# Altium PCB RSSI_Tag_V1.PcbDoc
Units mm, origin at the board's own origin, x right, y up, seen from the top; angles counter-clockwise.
Board outline 76.2 x 83.52 mm, 2 copper layers (Top Layer, Bottom Layer); 76 components, 47 nets, 358 pads, 24 vias.
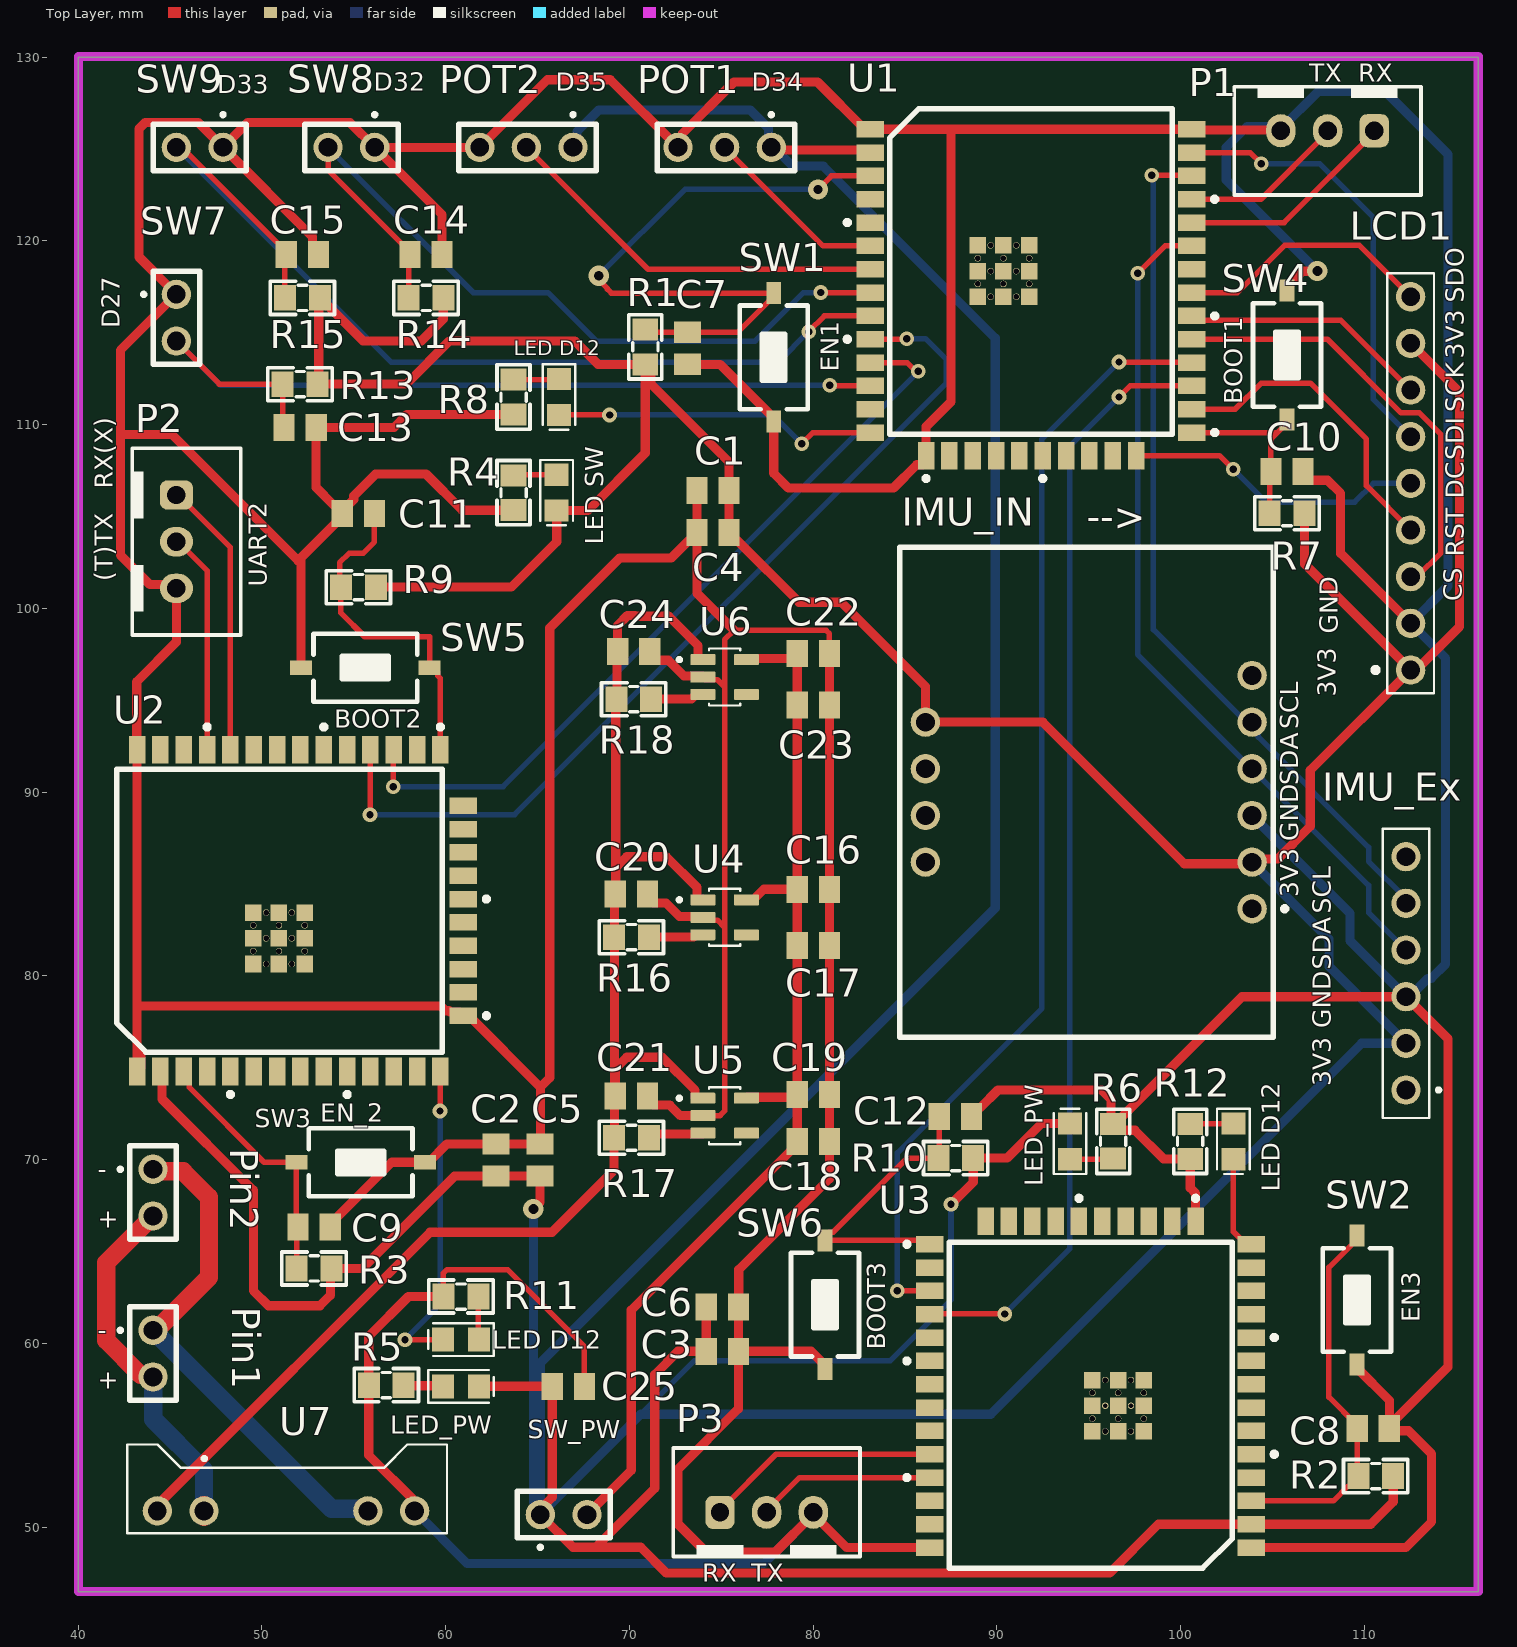
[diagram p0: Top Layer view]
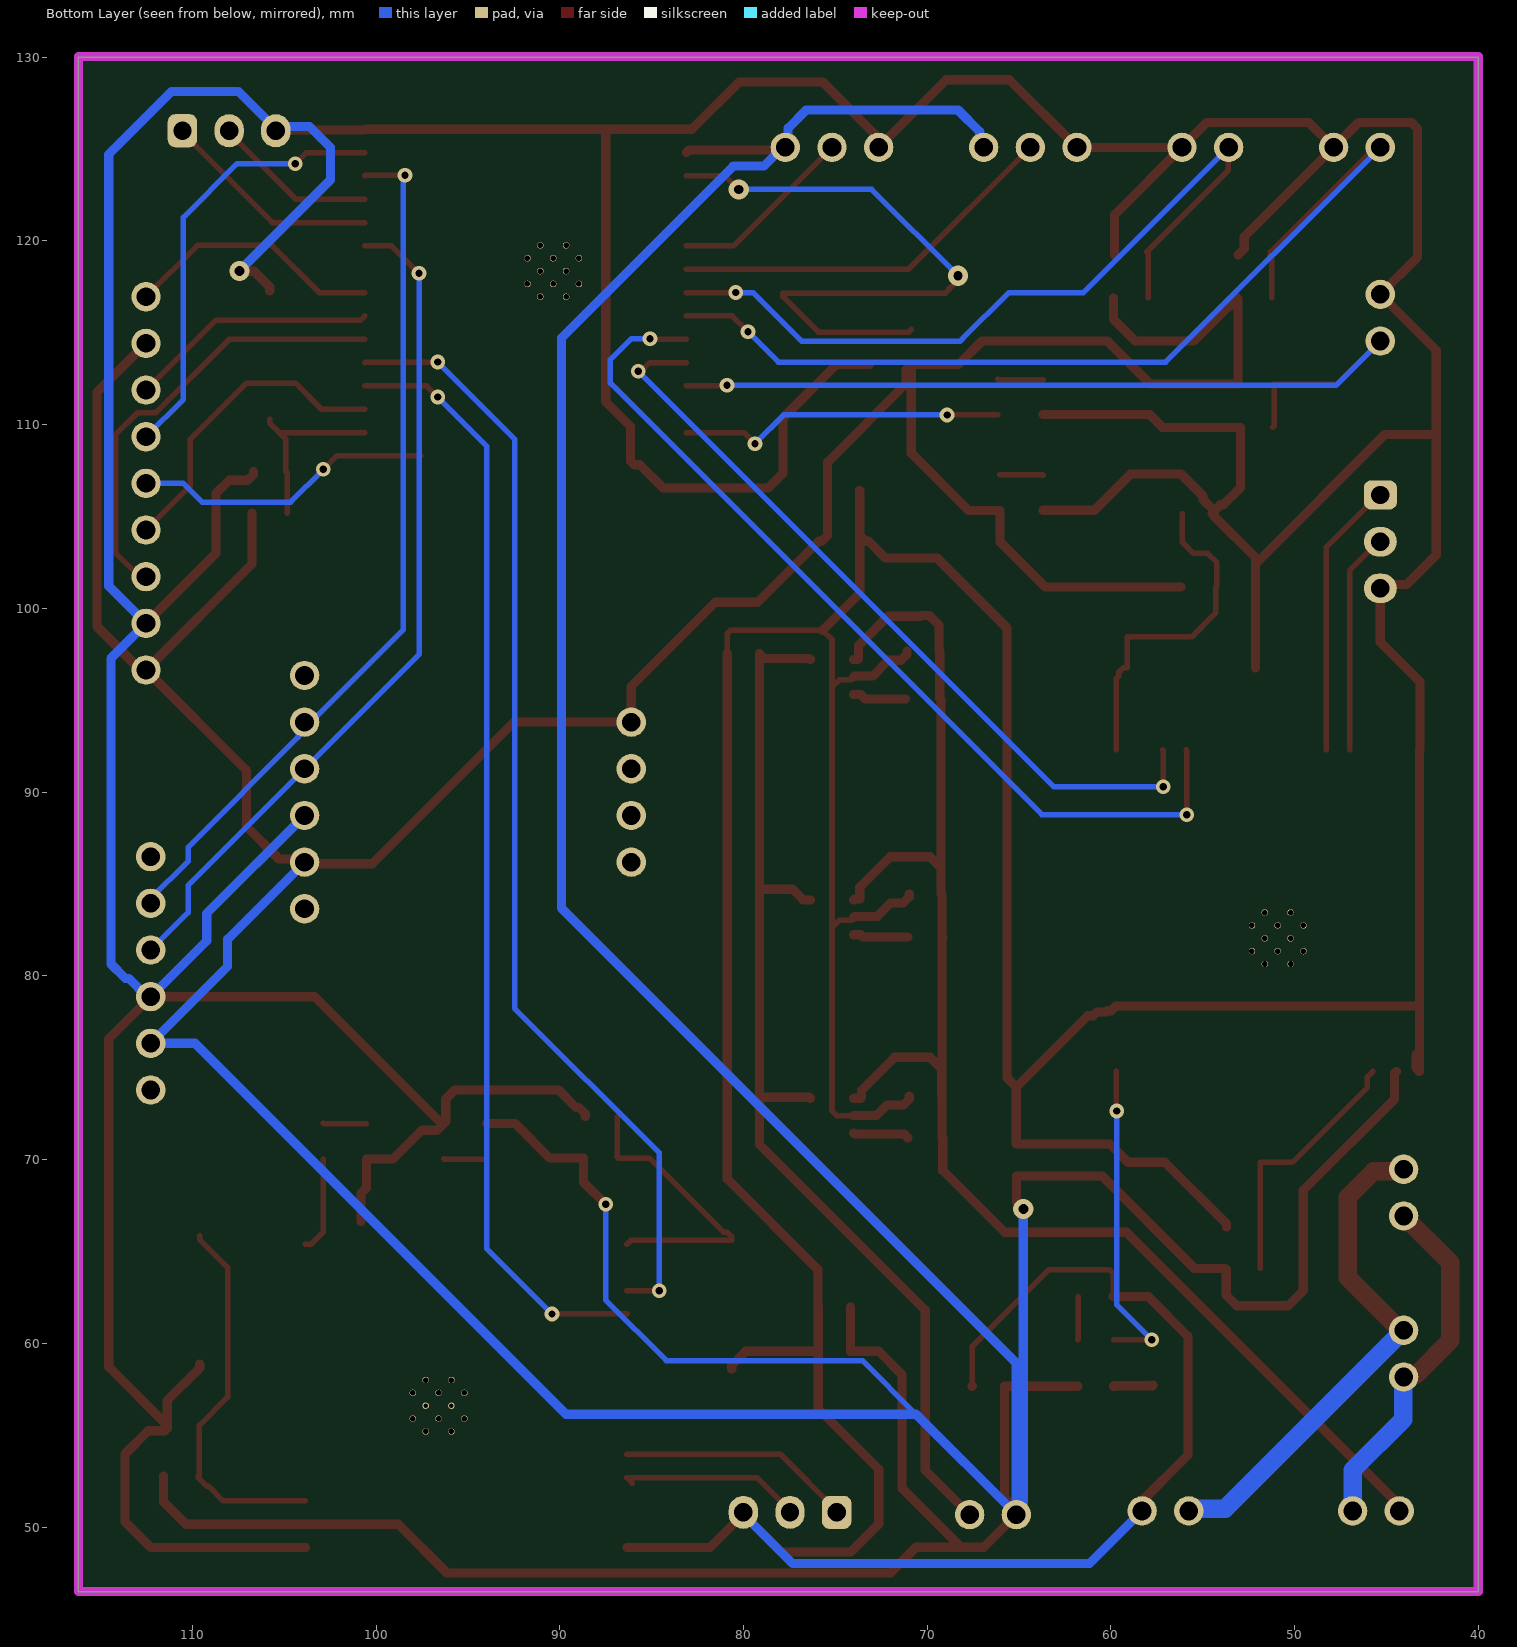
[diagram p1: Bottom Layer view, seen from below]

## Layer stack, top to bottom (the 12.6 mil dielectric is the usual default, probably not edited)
Top Solder: solder mask 0.0102, Solder Resist, Dk 3.5
Top Layer: signal copper 0.0356
Dielectric 1: dielectric 0.32, FR-4, Dk 4.8
Bottom Layer: signal copper 0.0356
Bottom Solder: solder mask 0.0102, Solder Resist, Dk 3.5

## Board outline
40.005,46.482 40.005,130 116.205,130 116.205,46.482

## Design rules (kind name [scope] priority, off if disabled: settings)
Clearance [All] p1: gap=0.3 ignorepadtopadclearanceinfootprint=FALSE
PolygonConnect [All] p1: connectstyle=Relief reliefconductorwidth=0.254 reliefentries=4 polygonreliefangle="90 Angle" airgapwidth=0.254
RoutingVias [All] p1: holewidth=0.711 width=1.27 viastyle="Through Hole" minholewidth=0.711 minwidth=1.27 maxholewidth=0.711 maxwidth=1.27
SolderMaskExpansion [All] p1: expansion=0.102 istentingtop=FALSE
Width POW [InNetClass('POW')] p1: maxlimit=1 minlimit=0.3 preferedwidth=0.5
Width RON [InNetClass('RON')] p2: maxlimit=0.5 minlimit=0.3 preferedwidth=0.3
30 further rules are at their usual default settings.

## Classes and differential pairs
net class RON: BOOT BOOT_2 BOOT_3 D2/SPI_DC D4/SPI_RST D5/SPI_CS D12/LED1 D12/LED1_2 D12/LED1_3 D18/SPI_SCK D19/SPI_SDO D23/SPI_SDI D27 D32 D33 D34_Pot1 D35_Pot2 EN EN_2 EN_3 NetLED1_2 NetLED2_2 NetLED3_2 NetLED4_2 NetLED5_2 NetLED6_2 NetR16_2 NetR17_2 NetR18_2 RX0 RX0_2 RX0_3 RX1/TX2_2 RX2/TX2_3 SCL SDA TX0 TX0_2 TX0_3 TX1/RX2_2 TX2_RX2_3
net class POW: 3V3 GND O_3V3 VBAT+ VBAT- VOUT

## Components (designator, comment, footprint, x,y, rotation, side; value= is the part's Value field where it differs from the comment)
C1 "10uF" Capacitor_0805 74.549,106.426 r180 top
C2 "10uF" Capacitor_0805 62.738,69.977 r90 top
C3 "10uF" Capacitor_0805 75.057,59.563 r0 top
C4 "0.1uF" Capacitor_0805 74.549,104.14 r180 top
C5 "0.1uF" Capacitor_0805 65.138,69.977 r90 top
C6 "0.1uF" Capacitor_0805 75.057,61.976 r0 top
C7 "10uF" Capacitor_0805 73.152,114.159 r270 top
C8 "10uF" Capacitor_0805 110.49,55.372 r0 top
C9 "10uF" Capacitor_0805 52.832,66.335 r0 top
C10 "10uF" Capacitor_0805 105.791,107.442 r0 top
C11 "10uF" Capacitor_0805 55.245,105.156 r180 top
C12 "10uF" Capacitor_0805 87.743,72.341 r0 top
C13 "10uF" Capacitor_0805 52.07,109.855 r0 top
C14 "10uF" Capacitor_0805 58.928,119.253 r0 top
C15 "10uF" Capacitor_0805 52.197,119.253 r0 top
C16 "47uF" Capacitor_0805 80.01,84.709 r0 top
C17 "0.1uF" Capacitor_0805 80.01,81.661 r0 top
C18 "47uF" Capacitor_0805 80.01,70.993 r0 top
C19 "0.1uF" Capacitor_0805 80.01,73.533 r0 top
C20 "0.1uF" Capacitor_0805 70.104,84.455 r0 top
C21 "0.1uF" Capacitor_0805 70.104,73.447 r0 top
C22 "47uF" Capacitor_0805 80.01,97.536 r0 top
C23 "0.1uF" Capacitor_0805 80.01,94.742 r0 top
C24 "0.1uF" Capacitor_0805 70.231,97.663 r0 top
C25 "0.1uF" Capacitor_0805 66.675,57.658 r0 top
IMU_Ex "BNO055" BNO055_External 112.268,80.137 r90 top (schematic designator IMU_Ex1)
IMU_IN "BNO055" BNO055_Internal 95,90 r90 top
LCD1 "ILI9341" ILI9341_LCD3.5 112.522,106.807 r0 top
"LED D12" "Led" "Led 0805 Blue" 102.87,70.993 r90 top (schematic designator LED6)
"LED D12" "Led" "Led 0805 Blue" 60.833,60.198 r0 top (schematic designator LED5)
"LED D12" "Led" "Led 0805 Blue" 66.167,111.506 r90 top (schematic designator LED4)
"LED SW" "Led" "Led 0805 Blue" 66.04,106.299 r90 top (schematic designator LED1)
LED_PW "Led" "Led 0805 Blue" 93.98,70.993 r270 top (schematic designator LED3)
LED_PW "Led" "Led 0805 Blue" 60.833,57.658 r180 top (schematic designator LED2)
P1 "UART" HDR/Header/3/BOX 108,126 r270 top
P2 "UART" HDR/Header/3/BOX 45.339,103.632 r0 top
P3 "UART" HDR/Header/3/BOX 77.47,50.8 r90 top
Pin1 "JP_1x2" JP_1x2 44.069,59.436 r270 top (schematic designator Battery1)
Pin2 "JP_1x2" JP_1x2 44.069,68.199 r270 top (schematic designator Battery2)
POT1 "JP_1x3" JP_1x3 79.121,119.634 r180 top
POT2 "JP_1x3" JP_1x3 68.326,119.634 r180 top
R1 "10k" "tro smd 0805" 70.927,114.238 r270 top
R2 "10k" "tro smd 0805" 110.617,52.832 r0 top
R3 "10k" "tro smd 0805" 52.832,64.135 r0 top
R4 "1k" "tro smd 0805" 63.754,106.299 r270 top
R5 "1k" "tro smd 0805" 56.769,57.658 r180 top
R6 "1k" "tro smd 0805" 96.266,70.993 r90 top
R7 "10k" "tro smd 0805" 105.791,105.242 r0 top
R8 "1k" "tro smd 0805" 63.754,111.506 r270 top
R9 "10k" "tro smd 0805" 55.245,101.219 r0 top
R10 "10k" "tro smd 0805" 87.757,70.14 r0 top
R11 "1k" "tro smd 0805" 60.833,62.484 r180 top
R12 "1k" "tro smd 0805" 100.584,70.993 r270 top
R13 "10k" "tro smd 0805" 52.07,112.268 r0 top
R14 "10k" "tro smd 0805" 58.928,116.967 r0 top
R15 "10k" "tro smd 0805" 52.197,116.967 r0 top
R16 "1k" "tro smd 0805" 70.104,82.169 r0 top
R17 "1k" "tro smd 0805" 70.104,71.247 r0 top
R18 "1k" "tro smd 0805" 70.231,95.123 r0 top
SW1 "SW" SW1-SMD 77.851,113.665 r90 top value="SW chip 2 pin"
SW2 "SW" SW1-SMD 109.601,62.357 r90 top value="SW chip 2 pin"
SW3 "SW" SW1-SMD 55.372,69.85 r180 top value="SW chip 2 pin"
SW4 "SW" SW1-SMD 105.791,113.792 r270 top value="SW chip 2 pin"
SW5 "SW" SW1-SMD 55.626,96.774 r0 top value="SW chip 2 pin"
SW6 "SW" SW1-SMD 80.645,62.103 r90 top value="SW chip 2 pin"
SW7 "JP_1x2" JP_1x2 45.339,115.824 r270 top
SW8 "JP_1x2" JP_1x2 54.864,125.095 r180 top
SW9 "JP_1x2" JP_1x2 46.609,125.095 r180 top
SW_PW "SW_POWER" JP_1x2 66.421,50.673 r0 top (schematic designator jp_1)
U1 "ESP32_WROOM_32U" ESP32_WROOM_32U#1 91.859,117.201 r0 top
U2 "ESP32_WROOM_32U" ESP32_WROOM_32U#1 52.084,83.545 r90 top
U3 "ESP32_WROOM_32U" ESP32_WROOM_32U#2 95.1,57.76 r180 top
U4 "AP2112K-3.3TRG1" SOT95P285X140-5N 75.184,83.185 r0 top
U5 "AP2112K-3.3TRG1" SOT95P285X140-5N 75.184,72.39 r0 top
U6 "AP2112K-3.3TRG1" SOT95P285X140-5N 75.184,96.266 r0 top
U7 "TP4056_charger" TP4056_charger 51.305,39.376 r90 top

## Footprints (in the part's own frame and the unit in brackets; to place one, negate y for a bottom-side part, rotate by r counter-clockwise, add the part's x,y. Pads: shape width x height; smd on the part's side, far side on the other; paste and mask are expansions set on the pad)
BNO055_External [mm]
  round 1.6 hole 1.02 mask+0.1: 1(-6.35,0) 2(-3.81,0) 3(-1.27,0) 4(1.27,0) 5(3.81,0) 6(6.35,0)
  silkscreen extent -7.87,-1.88 7.87,1.27, body extent -8.75,-2.16 8.75,3.59, height 7.1
BNO055_Internal [mm]
  round 1.6 hole 1.02 mask+0.1: 1(-6.35,-8.89) 2(-3.81,-8.89) 3(-1.27,-8.89) 4(1.27,-8.89) 5(3.81,-8.89) 6(6.35,-8.89) 7(3.81,8.89) 8(1.27,8.89) 9(-1.27,8.89) 10(-3.81,8.89)
  silkscreen extent -13.33,-10.77 13.33,10.29, body extent -13.33,-10.12 13.33,10.29, height 9.15
Capacitor_0805 [mm]
  rect 1.16x1.47 smd: 1(-0.875,0) 2(0.875,0)
  body extent -1,-0.6 1,0.6, height 1.2
ESP32_WROOM_32U#1 [mm]
  rect 1.5x0.9 smd: 1(-8.75,8.88) 2(-8.75,7.61) 3(-8.75,6.34) 4(-8.75,5.07) 5(-8.75,3.8) 6(-8.75,2.53) 7(-8.75,1.26) 8(-8.75,-0.01) 9(-8.75,-1.28) 10(-8.75,-2.55) 11(-8.75,-3.82) 12(-8.75,-5.09) 13(-8.75,-6.36) 14(-8.75,-7.63) 25(8.75,-7.63) 26(8.75,-6.36) 27(8.75,-5.09) 28(8.75,-3.82) 29(8.75,-2.55) 30(8.75,-1.28) 31(8.75,-0.01) 32(8.75,1.26) 33(8.75,2.53) 34(8.75,3.8) 35(8.75,5.07) 36(8.75,6.34) 37(8.75,7.61) 38(8.75,8.88)
  rect 0.9x1.5 smd: 15(-5.715,-8.88) 16(-4.445,-8.88) 17(-3.175,-8.88) 18(-1.905,-8.88) 19(-0.635,-8.88) 20(0.635,-8.88) 21(1.905,-8.88) 22(3.175,-8.88) 23(4.445,-8.88) 24(5.715,-8.88)
  rect 0.9x0.9 smd: 39_1(-2.9,2.56) 39_2(-1.5,2.56) 39_3(-0.1,2.56) 39_4(-2.9,1.16) 39_5(-1.5,1.16) 39_6(-0.1,1.16) 39_7(-2.9,-0.24) 39_8(-1.5,-0.24) 39_9(-0.1,-0.24)
  round 0.35 hole 0.3 mask+0: 40_1(-2.2,2.56) 40_2(-0.8,2.56) 40_3(-2.9,1.86) 40_4(-1.5,1.86) 40_5(-0.1,1.86) 40_6(-2.2,1.16) 40_7(-0.8,1.16) 40_8(-2.9,0.46) 40_9(-1.5,0.46) 40_10(-0.1,0.46) 40_11(-2.2,-0.24) 40_12(-0.8,-0.24)
  silkscreen extent -10.1,-10.23 10.1,10, body extent -9,-9.13 9,10.07, height 3.35
ESP32_WROOM_32U#2 [mm]
  rect 1.5x0.9 smd: 1(-8.75,8.88) 2(-8.75,7.61) 3(-8.75,6.34) 4(-8.75,5.07) 5(-8.75,3.8) 6(-8.75,2.53) 7(-8.75,1.26) 8(-8.75,-0.01) 9(-8.75,-1.28) 10(-8.75,-2.55) 11(-8.75,-3.82) 12(-8.75,-5.09) 13(-8.75,-6.36) 14(-8.75,-7.63) 25(8.75,-7.63) 26(8.75,-6.36) 27(8.75,-5.09) 28(8.75,-3.82) 29(8.75,-2.55) 30(8.75,-1.28) 31(8.75,-0.01) 32(8.75,1.26) 33(8.75,2.53) 34(8.75,3.8) 35(8.75,5.07) 36(8.75,6.34) 37(8.75,7.61) 38(8.75,8.88)
  rect 0.9x1.5 smd: 15(-5.715,-8.88) 16(-4.445,-8.88) 17(-3.175,-8.88) 18(-1.905,-8.88) 19(-0.635,-8.88) 20(0.635,-8.88) 21(1.905,-8.88) 22(3.175,-8.88) 23(4.445,-8.88) 24(5.715,-8.88)
  rect 0.9x0.9 smd: 39_1(-2.9,2.56) 39_2(-1.5,2.56) 39_3(-0.1,2.56) 39_4(-2.9,1.16) 39_5(-1.5,1.16) 39_6(-0.1,1.16) 39_7(-2.9,-0.24) 39_8(-1.5,-0.24) 39_9(-0.1,-0.24)
  round 0.35 hole 0.3 mask+0: 40_1(-2.2,2.56) 40_2(-0.8,2.56) 40_3(-2.9,1.86) 40_4(-1.5,1.86) 40_5(-0.1,1.86) 40_8(-2.9,0.46) 40_9(-1.5,0.46) 40_10(-0.1,0.46) 40_11(-2.2,-0.24) 40_12(-0.8,-0.24)
  round 0.35 hole 0.25 mask+0: 40_6(-2.2,1.16) 40_7(-0.8,1.16)
  silkscreen extent -10.1,-10.23 10.1,10, body extent -9,-9.13 9,10.07, height 3.35
HDR/Header/3/BOX [mm]
  rrect50% 1.8x1.6 hole 1: 1(0,2.54)
  oval 1.8x1.6 hole 1: 2(0,0) 3(0,-2.54)
  silkscreen extent -2.41,-5.08 3.5,5.08, body extent -2.29,-5 3.41,5, height 7
ILI9341_LCD3.5 [mm]
  round 1.6 hole 1.02 mask+0.1: 1(0,-10.16) 2(0,-7.62) 3(0,-5.08) 4(0,-2.54) 5(0,0) 6(0,2.54) 7(0,5.08) 8(0,7.62) 9(0,10.16)
  silkscreen extent -2.03,-11.43 1.27,11.43, body extent -3.56,-12.5 2.19,12.5, height 7.1
JP_1x2 [mm] "CWF2 (DS1069-1x2)"
  round 1.6 hole 1.02 mask+0.1: 1(-1.27,0) 2(1.27,0)
  silkscreen extent -2.54,-1.88 2.54,1.27, body extent -3.77,-2.2 3.73,3.55, height 7
JP_1x3 [mm] "CWF3 (DS1069-1x3)"
  round 1.6 hole 1.02 mask+0.1: 1(1.397,-5.461) 2(3.937,-5.461) 3(6.477,-5.461)
  silkscreen extent 0.13,-7.34 7.62,-4.19, body extent -1.06,-7.66 8.94,-1.9, height 7.1
"Led 0805 Blue" [mm]
  rect 1.2x1.3 smd: 1(-0.975,0) 2(0.975,0)
  silkscreen extent -1.78,-0.89 1.78,0.89, body extent -1.01,-0.62 1.01,0.63, height 1.1
SOT95P285X140-5N [mm]
  rrect15% 1.35x0.6 smd: 1(-1.185,0.95) 2(-1.185,0) 3(-1.185,-0.95) 4(1.185,-0.95) 5(1.185,0.95)
  silkscreen extent -2.57,-1.55 0.85,1.55, body extent -1.5,-1.4 1.5,1.4, height 1.4
SW1-SMD [mm]
  rect 1.2x0.8 smd: 1(-3.5,0) 2(3.5,0)
  silkscreen extent -2.82,-1.85 2.82,1.85, body extent -3.05,-1.85 3.05,1.85, height 2.5
TP4056_charger [mm]
  round 1.6 hole 1.02 mask+0.1: 1(11.5,4.46) 2(11.5,-4.46) 3(11.5,7) 4(11.5,-7)
  silkscreen extent 10.29,-8.76 15.11,8.64, body extent -14.19,-8.76 15.11,8.64, height 9.34
"tro smd 0805" [mm]
  rect 1.2x1.4 smd: 1(-0.946,-0.061) 2(0.954,-0.061)
  silkscreen extent -1.75,-0.97 1.75,0.84, body extent -1.56,-0.76 1.44,0.64, height 0.53

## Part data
C1 C2 C3 C4 C5 C6 C7 C8 C9 C10 C11 C12 C13 C14 C15 C16 C17 C18 C19 C20 C21 C22 C23 C24 C25: library part Capacitor_0805, "Capacitor; Ceramic; Cap; .220uF; Tol 10%; SMT; Vol-Rtg 50V; X7R; Tape And Reel"
IMU_Ex: library part BNO055_External
LCD1: library part ILI9341_LCD3.5
"LED D12" "LED D12" "LED D12" "LED SW" LED_PW LED_PW: "Typical LED"
P1 P2 P3: library part "Header 3", "Header, 3-Pin"
R1 R2 R3 R7 R9 R10 R13 R14 R15: library part "Tro 0805 1% 10k", "Dán"
R4 R5 R6 R8 R11 R12 R16 R17 R18: library part "Tro 0805 1% 1k", "Dán"
SW1 SW2 SW3 SW4 SW5 SW6: library part SW2, "Switch button 2 pin"
SW_PW: library part JP_1x2
U1 U2 U3: "Bluetooth, WiFi 802.11b/g/n, Bluetooth v4.2 +EDR, Class 1, 2 and 3 Transceiver Module 2.4GHz ~ 2.5GHz Antenna Not Included, U.FL Surface Mount"
U4 U5 U6: "Linear Voltage Regulator IC Positive Fixed 1 Output 600mA SOT-25", Package="SOT-753 Diodes Inc."

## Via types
v1: diameter 0.8, hole 0.4, Top Layer to Bottom Layer, 20 vias
v2: diameter 1.1, hole 0.5, Top Layer to Bottom Layer, 2 vias
v3: diameter 1.1, hole 0.55, Top Layer to Bottom Layer, 2 vias

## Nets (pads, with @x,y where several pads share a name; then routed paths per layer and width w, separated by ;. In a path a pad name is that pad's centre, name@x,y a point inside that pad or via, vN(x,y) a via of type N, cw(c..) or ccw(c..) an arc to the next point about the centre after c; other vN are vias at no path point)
3V3: "LED SW.1" C1.1 C2.1 C3.1 C4.1 C5.1 C6.1 C25.1 IMU_Ex.2 IMU_IN.2 IMU_IN.7 LCD1.1 LCD1.8 LED_PW.1 POT1.1 POT2.1 R1.2 R2.2 R3.2 R7.2 R9.2 R10.2 R13.2 R14.2 R15.2 SW_PW.1 U1.2 U2.2 U3.2 | length 494.8
  Top Layer w0.5: U2.2 44.561,74.708 44.561,73.295 49.53,68.326 49.53,62.865 50.355,62.039 53.149,62.039 53.721,62.611 53.721,64.009 R3.2 55.456,64.074 60.484,69.102 C2.1 C5.1 65.138,67.678 v3(64.77,67.31) ; R15.2@53.088,116.843 53.088,112.271 R13.2 57.851,112.207 60.198,114.554 67.021,114.554 68.291,113.284 R1.2 ; R15.2 53.151,116.806 53.501,116.456 53.601,116.456 55.504,114.554 58.674,114.554 59.869,115.749 R14.2@59.869,116.893 ; R9.2 63.566,101.158 66.04,103.632 66.04,105.324 67.732,105.324 70.866,108.458 R1.2@70.866,112.934 ; LED_PW.1@61.808,57.658 C25.1 65.8,51.62 65.151,50.971 SW_PW.1 66.929,48.895 68.16,48.895 ; R1.2@70.921,112.989 71.161,112.989 71.161,112.227 75.424,107.964 C1.1 C4.1 75.424,103.985 75.754,103.655 75.909,103.655 79.234,100.33 81.534,100.33 86.11,95.754 IMU_IN.7 92.499,93.81 100.203,86.106 103.806,86.106 IMU_IN.2 104.06,86.36 105.283,86.36 107.061,88.138 107.061,91.186 LCD1.1 ; C6.1 C3.1 72.644,59.563 71.374,58.293 71.374,52.109 68.16,48.895 ; POT1.1 77.866,124.953 82.967,124.953 U1.2 ; v1(87.503,67.564) 88.711,68.772 R10.2 90.552,70.08 92.44,71.968 LED_PW.1@93.98,71.968 ; R7.2 106.745,102.424 LCD1.1 ; R2.2 111.571,51.373 110.348,50.15 U3.2 98.791,50.15 96.139,47.498 72.009,47.498 70.612,48.895 68.16,48.895 ; LCD1.8 115.189,111.76 115.189,99.016 112.82,96.647 LCD1.1
  Bottom Layer w0.3: 70.612,56.134 73.533,59.055 84.201,59.055 87.503,62.357 v1(87.503,67.564)
  Bottom Layer w0.5: SW_PW.1@64.77,51.352 v3(64.77,67.31) ; SW_PW.1 65.151,58.928 89.916,83.693 89.916,114.713 80.554,124.075 78.896,124.075 77.875,125.095 POT1.1 77.572,125.247 77.572,126.136 76.581,127.127 68.326,127.127 67.139,125.94 67.139,125.305 POT2.1 ; SW_PW.1@65.3,50.822 70.612,56.134 89.662,56.134 109.855,76.327 IMU_Ex.2 108.079,80.516 108.079,82.001 IMU_IN.2
BOOT: C10.1 R7.1 SW4.2 U1.25 | length 10.2
  Top Layer w0.3: U1.25 105.27,109.571 ; R7.1 104.845,107.371 C10.1 104.916,109.217 105.27,109.571 ; SW4.2 105.791,110.092 105.27,109.571
BOOT_2: C11.1 R9.1 SW5.2 U2.25 | length 18.5
  Top Layer w0.3: C11.1 56.12,103.618 55.499,102.997 54.737,102.997 54.229,102.489 54.229,101.229 R9.1 54.299,99.752 55.594,98.457 59.126,98.457 SW5.2 59.326,96.774 59.576,96.524 59.576,96.324 59.714,96.186 U2.25
BOOT_3: C12.1 R10.1 SW6.2 U3.25 | length 16.2
  Top Layer w0.3: U3.25 86.137,65.603 SW6.2 80.645,65.803 80.895,66.053 81.095,66.053 85.122,70.08 R10.1 86.868,70.136 C12.1
D2/SPI_DC: LCD1.5 U1.24 | length 16.4
  Top Layer w0.3: U1.24 102.118,108.321 v1(102.87,107.569)
  Bottom Layer w0.3: v1(102.87,107.569) 104.648,105.791 109.474,105.791 110.49,106.807 LCD1.5
D4/SPI_RST: LCD1.4 U1.26 | length 17.3
  Top Layer w0.3: U1.26 102.967,110.841 104.394,112.268 107.061,112.268 110.109,109.22 110.109,106.68 LCD1.4
D5/SPI_CS: LCD1.3 U1.29 | length 24.3
  Top Layer w0.3: U1.29 107.99,114.651 112.004,110.637 113,110.637 114.173,109.464 114.173,103.026 112.874,101.727 LCD1.3
D12/LED1: "LED D12.1"@66.167,110.531 U1.14 | length 17.9
  Top Layer w0.3: 66.167,110.531 v1(68.92,110.531) v1@68.961,110.49 ; v1(79.375,108.966) 79.98,109.571 U1.14
  Bottom Layer w0.3: v1(68.92,110.531) 77.81,110.531 v1(79.375,108.966)
D12/LED1_2: "LED D12.1"@59.858,60.198 U2.14 | length 17.2
  Top Layer w0.3: v1@58.039,60.198 59.858,60.198 ; v1(59.69,72.644) 59.714,72.668 U2.14
  Bottom Layer w0.3: v1(57.785,60.198) 59.69,62.103 v1(59.69,72.644)
D12/LED1_3: "LED D12.1"@102.87,70.018 U3.14 | length 5.2
  Top Layer w0.3: 102.87,70.018 102.87,66.07 103.55,65.39 U3.14
D18/SPI_SCK: LCD1.7 U1.30 | length 13.6
  Top Layer w0.3: U1.30 100.833,115.697 108.712,115.697 LCD1.7
D19/SPI_SDO: LCD1.9 U1.31 | length 14.1
  Top Layer w0.3: U1.31 103.094,117.191 105.664,119.761 109.728,119.761 LCD1.9
D23/SPI_SDI: LCD1.6 U1.37 | length 24.1
  Top Layer w0.3: U1.37 103.789,124.811 v1(104.394,124.206)
  Bottom Layer w0.3: v1(104.394,124.206) 107.569,124.206 110.49,121.285 110.49,111.379 LCD1.6
D27: C13.1 R13.1 SW7.2 U1.12 | length 47.7
  Top Layer w0.3: SW7.2 47.686,112.207 R13.1 51.124,109.926 C13.1 ; v1@81.153,112.141 81.183,112.111 U1.12
  Bottom Layer w0.3: SW7.2 47.752,112.141 v1(80.899,112.141)
D32: C14.1 R14.1 SW8.2 U1.8 | length 45.1
  Top Layer w0.3: SW8.2 53.616,125.073 53.616,123.845 58.053,119.408 57.982,119.337 R14.1 ; v1@80.391,117.221 v1(80.421,117.191) U1.8
  Bottom Layer w0.3: SW8.2 61.498,117.191 65.562,117.191 68.073,114.68 68.199,114.554 76.835,114.554 79.472,117.191 v1(80.421,117.191)
D33: C15.1 R15.1 SW9.2 U1.9 | length 54.5
  Top Layer w0.3: SW9.2 45.635,125.095 51.322,119.408 C15.1 51.251,119.182 R15.1 ; v1(79.756,115.062) 80.615,115.921 U1.9
  Bottom Layer w0.3: SW9.2 57.023,113.411 78.105,113.411 v1(79.756,115.062)
D34_Pot1: POT1.2 U1.6 | length 10.1
  Top Layer w0.3: POT1.2 80.548,119.731 U1.6
D35_Pot2: POT2.2 U1.7 | length 21.5
  Top Layer w0.3: POT2.2 71.023,118.461 U1.7
EN: C7.1 R1.1 SW1.2 U1.3 | length 35.1
  Top Layer w0.3: v2(68.326,118.11) 68.326,117.894 68.8,117.419 68.8,117.382 69.017,117.165 SW1.2 77.851,116.965 75.92,115.034 C7.1 71.016,115.034 R1.1 ; v2(80.264,122.809) 80.996,123.541 U1.3
  Bottom Layer w0.3: v2(68.326,118.11) 73.025,122.809 v2(80.264,122.809)
EN_2: C9.1 R3.1 SW3.2 U2.3 | length 14.3
  Top Layer w0.3: U2.3 46.044,74.495 46.044,73.929 50.123,69.85 SW3.2 51.872,66.279 51.886,66.265 R3.1
EN_3: C8.1 R2.1 SW2.2 U3.3 | length 20.8
  Top Layer w0.3: U3.3 108.32,51.42 109.121,52.221 109.221,52.221 109.671,52.671 R2.1 109.615,52.828 C8.1 109.615,55.527 108.077,57.065 108.077,64.133 109.601,65.657 SW2.2
GND: C1.2 C2.2 C3.2 C4.2 C5.2 C6.2 C7.2 C8.2 C9.2 C10.2 C11.2 C12.2 C13.2 C14.2 C15.2 C16.2 C17.2 C18.2 C19.2 C20.2 C21.2 C22.2 C23.2 C24.2 C25.2 IMU_Ex.3 IMU_IN.3 LCD1.2 P1.3 P2.3 P3.3 POT1.3 POT2.3 R4.2 R5.2 R6.2 R8.2 R11.2 R12.2 SW1.1 SW2.1 SW3.1 SW4.1 SW5.1 SW6.1 SW7.1 SW8.1 SW9.1 U1.1 U1.15 U1.38 U2.1 U2.15 U2.38 U3.1 U3.15 U3.38 U4.2 U5.2 U6.2 U7.4 | length 668.3
  Top Layer w0.3: R11.2 59.879,63.816 60.074,64.011 63.37,64.011 67.55,59.831 C25.2 ; U5.2 74.93,72.39 75.184,72.644 75.184,82.635 ; U4.2 74.149,83.035 74.784,83.035 75.184,82.635 ; U6.2 74.149,96.116 74.784,96.116 75.184,95.716 ; C22.2 80.885,98.63 80.709,98.806 75.692,98.806 75.184,98.298 75.184,95.716 ; 75.184,82.635 75.184,95.716
  Top Layer w0.5: 43.404,75.703 43.404,74.995 U2.1 43.204,74.995 43.204,75.703 43.204,78.359 ; SW5.1 52.126,102.433 ; C15.2 52.742,119.583 52.742,120.232 SW9.1 ; C9.2 53.707,66.49 57.067,69.85 SW3.1 59.072,69.85 60.074,70.852 C2.2 C5.2 65.151,70.865 65.151,73.943 ; C11.2@54.497,105.184 C11.2@54.37,105.311 ; U7.4@58.42,51.308 55.815,53.913 R5.2 55.815,60.387 57.973,62.545 R11.2 ; C14.2 59.803,121.426 SW8.1 ; R4.2 60.898,105.345 58.928,107.315 56.186,107.315 54.99,106.119 54.99,105.931 C11.2@54.37,105.311 ; R8.2 57.889,110.552 57.192,109.855 C13.2 52.945,106.581 53.885,105.641 54.04,105.641 C11.2@54.37,105.311 ; C25.2 C25.2@67.557,57.651 ; C21.2 70.979,73.292 71.309,72.962 72.199,72.962 72.771,72.39 U5.2 ; C20.2 70.979,84.3 71.309,83.97 71.986,83.97 72.721,83.235 73.949,83.235 U4.2 ; C24.2 71.106,97.508 71.436,97.178 72.113,97.178 72.975,96.316 73.949,96.316 U6.2 ; C7.2 74.932,113.284 77.851,110.365 SW1.1 77.851,107.354 78.652,106.553 84.376,106.553 85.644,107.821 85.944,107.821 86.144,108.021 86.144,109.893 87.503,111.252 87.503,126.081 ; C1.2 C4.2 C4.2@73.674,103.985 ; 75.692,98.806 73.674,100.824 C4.2@73.674,103.985 ; P3.3 P3.3@80.01,50.7 ; SW6.1 80.645,58.803 79.885,59.563 C3.2 ; C22.2 C23.2 C16.2 C17.2 C19.2 C18.2 80.885,68.947 75.946,64.008 75.946,61.99 C6.2 C3.2 ; U3.38 81.83,48.88 P3.3@80.01,50.7 ; C12.2 88.618,72.496 88.948,72.826 89.103,72.826 90.064,73.787 95.719,73.787 96.209,73.297 96.209,72.066 R6.2 ; U3.15 100.815,68.168 100.523,68.46 R12.2 99.073,70.039 97.514,71.597 96.677,71.597 R6.2 ; U3.1 112.253,48.88 113.665,50.292 113.665,53.975 112.402,55.238 111.499,55.238 C8.2 ; P1.3 105.419,126.04 100.65,126.04 U1.38 87.503,126.081 ; SW4.1 105.791,117.492 106.648,118.349 107.427,118.349 v3(107.442,118.364) ; C10.2 106.666,107.306 106.996,106.976 107.996,106.976 108.712,106.26 108.712,102.997 LCD1.2 ; SW2.1 109.601,58.657 111.365,56.893 111.365,55.527 114.554,58.716 114.554,76.581 IMU_Ex.3 103.346,78.867 96.427,71.947 R6.2 ; 42.291,109.601 42.291,114.046 SW7.1 43.307,119.126 43.307,126.111 43.641,126.445 46.529,126.445 SW9.1 ; 42.291,109.601 42.291,102.909 43.897,101.302 45.129,101.302 P2.3 45.339,98.171 43.18,96.012 43.18,92.319 U2.38 43.204,78.359 ; 42.291,109.601 42.418,109.474 45.085,109.474 51.964,102.595 52.126,102.433 ; 43.204,78.359 59.727,78.359 59.986,78.1 60.171,78.1 60.241,78.03 60.764,78.03 U2.15 61.264,77.83 65.151,73.943 ; SW9.1 49.229,126.445 54.784,126.445 SW8.1 ; 52.126,102.433 52.126,102.757 54.37,105.001 C11.2 C11.2@54.37,105.311 ; SW8.1 POT2.3 65.532,128.778 68.961,128.778 POT1.3 72.854,125.305 72.854,125.813 75.692,128.651 80.239,128.651 82.809,126.081 U1.1 87.503,126.081 ; 65.151,73.943 65.659,74.451 65.659,98.933 69.469,102.743 72.277,102.743 73.189,103.655 73.344,103.655 C4.2@73.674,103.985 ; C3.2 75.932,56.43 72.644,53.142 72.644,50.165 74.168,48.641 77.951,48.641 P3.3@80.01,50.7
  Bottom Layer w0.3: U7.4@58.305,50.788 U7.4
  Bottom Layer w0.5: U7.4 61.175,48.006 77.316,48.006 80.01,50.7 P3.3 P3.3@79.808,50.598 ; IMU_IN.3 109.22,83.4 109.22,81.915 IMU_Ex.3 112.472,78.867 113.466,79.861 113.643,79.861 114.427,80.645 114.427,97.282 LCD1.2 114.554,101.219 114.554,124.714 111.125,128.143 107.503,128.143 105.46,126.1 P1.3 105.222,126.238 103.632,126.238 102.489,125.095 102.489,123.317 v3(107.442,118.364)
NetLED1_2: "LED SW.2" R4.1 | length 2.4
  Top Layer w0.3: R4.1 63.723,107.274 66.04,107.274
NetLED2_2: LED_PW.2@59.858,57.658 R5.1 | length 2.2
  Top Layer w0.5: R5.1 57.745,57.688 59.828,57.688 LED_PW.2@59.858,57.658
NetLED3_2: LED_PW.2@93.98,70.018 R6.1 | length 2.4
  Top Layer w0.3: LED_PW.2@93.98,70.018 96.297,70.018 R6.1
NetLED4_2: "LED D12.2"@66.167,112.481 R8.1 | length 2.5
  Top Layer w0.3: R8.1 66.138,112.452 66.167,112.481
NetLED5_2: "LED D12.2"@61.808,60.198 R11.1 | length 2.4
  Top Layer w0.3: R11.1 61.779,60.227 61.808,60.198
NetLED6_2: "LED D12.2"@102.87,71.968 R12.1 | length 2.4
  Top Layer w0.3: R12.1 102.841,71.939 102.87,71.968
NetR16_2: R16.2 U4.3 | length 3
  Top Layer w0.5: R16.2 73.497,82.108 73.624,82.235 U4.3
NetR17_2: R17.2 U5.3 | length 3
  Top Layer w0.5: R17.2 71.262,71.39 73.949,71.39 U5.3
NetR18_2: R18.2 U6.3 | length 2.9
  Top Layer w0.5: R18.2 73.37,95.062 73.624,95.316 U6.3
O_3V3: C16.1 C17.1 C18.1 C19.1 C22.1 C23.1 SW_PW.2 U4.5 U5.5 U6.5 | length 60.4
  Top Layer w0.5: SW_PW.2 70.104,53.086 70.104,61.807 79.135,70.838 C18.1 C19.1 ; U5.5 76.419,73.39 78.992,73.39 C19.1 ; U4.5 76.744,84.135 77.318,84.709 C16.1 ; U6.5 76.419,97.266 78.865,97.266 C22.1 C23.1 C16.1 ; C19.1 C17.1 C16.1
RX0: P1.1 U1.34 | length 12.1
  Top Layer w0.3: U1.34 105.641,121.001 110.54,125.9 P1.1
RX0_2: P2.1 U2.34 | length 15.2
  Top Layer w0.3: P2.1 45.439,106.172 48.284,103.327 U2.34
RX0_3: P3.1 U3.34 | length 12.8
  Top Layer w0.3: P3.1 74.93,50.9 77.99,53.96 U3.34
RX1/TX2_2: U1.10 U2.28 | length 50.5
  Top Layer w0.3: v1(55.88,88.773) 55.88,92.271 U2.28 ; U1.10 85.06,114.651 v1(85.09,114.681)
  Bottom Layer w0.3: v1(55.88,88.773) 63.754,88.773 87.249,112.268 87.249,113.538 86.106,114.681 v1(85.09,114.681)
RX2/TX2_3: U1.27 U3.28 | length 60.8
  Top Layer w0.3: U3.28@86.335,61.595 U3.28 86.365,61.595 v1(90.424,61.595) ; v1(96.647,111.506) 97.252,112.111 U1.27
  Bottom Layer w0.3: v1(90.424,61.595) 93.98,65.151 93.98,108.839 v1(96.647,111.506)
SCL: IMU_Ex.5 IMU_IN.5 U1.36 | length 47.8
  Top Layer w0.3: v1(98.425,123.571) 100.579,123.571 U1.36
  Bottom Layer w0.3: v1(98.425,123.571) 98.513,123.483 98.513,98.845 103.548,93.81 IMU_IN.5 103.89,93.458 104.239,93.109 104.239,92.992 110.236,86.995 110.236,86.233 112.268,84.201 IMU_Ex.5
SDA: IMU_Ex.4 IMU_IN.4 U1.33 | length 46.4
  Top Layer w0.3: v1(97.663,118.237) 99.157,119.731 U1.33
  Bottom Layer w0.3: v1(97.663,118.237) 97.663,97.497 110.236,84.924 110.236,83.439 IMU_Ex.4
TX0: P1.2 U1.35 | length 9
  Top Layer w0.3: U1.35 104.371,122.271 108,125.9 P1.2
TX0_2: P2.2 U2.35 | length 12.1
  Top Layer w0.3: P2.2 45.439,103.632 47.014,102.057 U2.35
TX0_3: P3.2 U3.35 | length 10.1
  Top Layer w0.3: P3.2 77.47,50.9 79.26,52.69 U3.35 U3.35@86.05,52.39
TX1/RX2_2: U1.11 U2.27 | length 42.8
  Top Layer w0.3: v1(57.15,90.297) 57.15,92.271 U2.27 ; U1.11 85.112,113.381 85.59,112.903 v1(85.725,112.903)
  Bottom Layer w0.3: v1(57.15,90.297) 63.119,90.297 v1(85.725,112.903)
TX2_RX2_3: U1.28 U3.27 | length 61.3
  Top Layer w0.3: v1(84.582,62.865) 86.335,62.865 U3.27 ; v1(96.647,113.411) 100.579,113.411 U1.28
  Bottom Layer w0.3: v1(84.582,62.865) 84.582,70.358 92.456,78.232 92.456,109.22 v1(96.647,113.411)
VBAT+: Pin1.2 Pin2.2 U7.1 | length 20.3
  Top Layer w1: Pin1.2 43.954,58.281 43.397,58.281 41.529,60.149 41.529,64.389 Pin2.2 ; U7.1@46.845,50.558 U7.1 U7.1@46.845,51.193
  Bottom Layer w1: Pin1.2 44.083,58.152 44.083,55.866 46.845,53.104 U7.1
VBAT-: Pin1.1 Pin2.1 U7.2 | length 28
  Top Layer w1: Pin1.1 44.231,60.706 47.117,63.592 47.117,67.945 45.708,69.354 44.184,69.354 Pin2.1
  Bottom Layer w1: Pin1.1 53.785,50.99 55.65,50.99 U7.2
VOUT: C20.1 C21.1 C24.1 R16.1 R17.1 R18.1 U4.1 U5.1 U6.1 U7.3 | length 82.3
  Top Layer w0.5: U7.3@44.42,51.308 59.152,66.04 65.786,66.04 69.158,69.412 R17.1 69.194,71.222 69.194,73.412 C21.1 ; U5.1 73.624,73.34 73.574,73.39 73.574,73.765 71.774,75.565 69.85,75.565 69.229,74.944 C21.1 ; U4.1 73.949,84.185 73.675,84.185 73.675,84.821 72.009,86.487 69.85,86.487 69.257,85.894 ; U6.1 73.789,97.216 73.739,97.266 73.739,97.965 72.136,99.568 70.358,99.568 70.311,99.615 69.897,99.615 69.356,99.074 C24.1 69.321,97.628 69.321,95.098 R18.1 69.257,95.034 69.257,85.894 ; C21.1 69.194,73.483 69.194,82.073 R16.1 69.194,82.144 69.194,84.42 C20.1 69.257,84.483 69.257,85.894
pads on no net: IMU_Ex.1 IMU_Ex.6 IMU_IN.1 IMU_IN.6 IMU_IN.8 IMU_IN.9 IMU_IN.10 U1.4 U1.5 U1.13 U1.16 U1.17 U1.18 U1.19 U1.20 U1.21 U1.22 U1.23 U1.32 U1.39_1 U1.39_2 U1.39_3 U1.39_4 U1.39_5 U1.39_6 U1.39_7 U1.39_8 U1.39_9 U1.40_1 U1.40_2 U1.40_3 U1.40_4 U1.40_5 U1.40_6 U1.40_7 U1.40_8 U1.40_9 U1.40_10 U1.40_11 U1.40_12 U2.4 U2.5 U2.6 U2.7 U2.8 U2.9 U2.10 U2.11 U2.12 U2.13 U2.16 U2.17 U2.18 U2.19 U2.20 U2.21 U2.22 U2.23 U2.24 U2.26 U2.29 U2.30 U2.31 U2.32 U2.33 U2.36 U2.37 U2.39_1 U2.39_2 U2.39_3 U2.39_4 U2.39_5 U2.39_6 U2.39_7 U2.39_8 U2.39_9 U2.40_1 U2.40_2 U2.40_3 U2.40_4 U2.40_5 U2.40_6 U2.40_7 U2.40_8 U2.40_9 U2.40_10 U2.40_11 U2.40_12 U3.4 U3.5 U3.6 U3.7 U3.8 U3.9 U3.10 U3.11 U3.12 U3.13 U3.16 U3.17 U3.18 U3.19 U3.20 U3.21 U3.22 U3.23 U3.24 U3.26 U3.29 U3.30 U3.31 U3.32 U3.33 U3.36 U3.37 U3.39_1 U3.39_2 U3.39_3 U3.39_4 U3.39_5 U3.39_6 U3.39_7 U3.39_8 U3.39_9 U3.40_1 U3.40_2 U3.40_3 U3.40_4 U3.40_5 U3.40_6 U3.40_7 U3.40_8 U3.40_9 U3.40_10 U3.40_11 U3.40_12 U4.4 U5.4 U6.4

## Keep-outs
Keep-Out Layer:
  lines w0.5: 40.005,46.482 116.205,46.482 116.205,130.048 40.005,130.048 40.005,46.482

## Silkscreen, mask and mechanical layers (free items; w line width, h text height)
Top Overlay:
  text "TX" at 106.99,128.674 h1
  text "RX" at 109.657,128.674 h1
  text "D32" at 56.071,128.166 h1
  text "D35" at 65.977,128.166 h1
  text "D34" at 76.645,128.166 h1
  text "D33" at 47.562,128.039 h1
  text "SDO" at 115.42,116.65 h1 r90
  text "D27" at 42.268,115.253 h1 r90
  text "3V3" at 115.42,113.602 h1 r90
  text "EN1" at 81.384,112.88 h1 r90
  text "BOOT1" at 103.355,111.118 h1 r90
  text "SCK" at 115.42,110.681 h1 r90
  text "SDI" at 115.42,108.054 h1 r90
  text "RX(X)" at 41.887,106.502 h1 r90
  text "DC" at 115.42,105.974 h1 r90
  text "-->" at 94.9,104.263 h1.5
  text "RST" at 115.42,102.807 h1 r90
  text "(T)TX" at 41.887,101.466 h1 r90
  text "UART2" at 50.269,101.172 h1 r90
  text "CS" at 115.293,100.386 h1 r90
  text "GND" at 108.562,98.616 h1 r90
  text "3V3" at 108.435,95.187 h1 r90
  text "BOOT2" at 53.928,93.495 h1
  text "SCL" at 106.403,93.409 h1 r90
  text "SDA" at 106.403,90.361 h1 r90
  text "GND" at 106.403,87.313 h1 r90
  text "3V3" at 106.403,84.265 h1 r90
  text "SCL" at 108.181,83.376 h1 r90
  text "SDA" at 108.181,80.328 h1 r90
  text "GND" at 108.181,77.153 h1 r90
  text "3V3" at 108.181,73.978 h1 r90
  text "EN_2" at 53.158,72.072 h1
  text "-" at 41.069,68.992 h1
  text "+" at 41.069,66.277 h1
  text "EN3" at 113.007,61.151 h1 r90
  text "-" at 41.069,60.229 h1
  text "BOOT3" at 83.924,59.643 h1 r90
  text "+" at 41.069,57.514 h1
  text "RX" at 73.97,47.013 h1
  text "TX" at 76.637,47.013 h1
